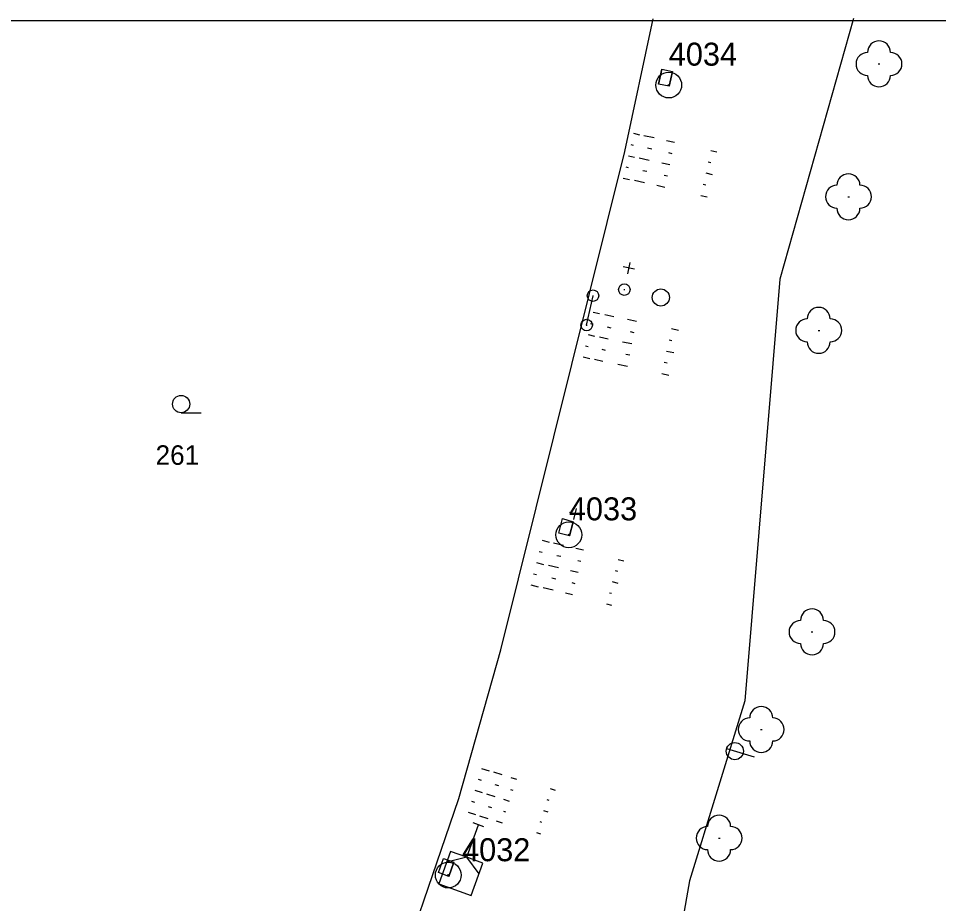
# Model space of a CAD drawing. Extents: x -558358 to -557517, y -1073786 to -1073189.
# Drawn here: x -558098.4 to -558018.3, y -1073267 to -1073189.9 of the extents above; entities that cross this region are included whole.
import ezdxf

# ---------------------------------------------------------------- set-up
doc = ezdxf.new("R2010")
doc.units = 0
for name, color, linetype in [('Body', 7, 'Continuous'), ('bubliny', 7, 'Continuous'), ('Drobná stavba - strom', 7, 'Continuous'), ('Návěst místo trati', 7, 'Continuous'), ('Parcelní čísla', 7, 'Continuous'), ('Přejezd - štěrkové lože', 7, 'Continuous'), ('Sonda - šrafa - vrstevnice', 7, 'Continuous'), ('Svazek obcí údolí Desné', 7, 'Continuous'), ('Vedení nerozlišené', 7, 'Continuous'), ('Vrstva 1', 7, 'Continuous'), ('Vrstva 60', 7, 'Continuous'), ('Značky kultur', 7, 'Continuous')]:
    doc.layers.add(name, color=color, linetype=linetype)

msp = doc.modelspace()

# ---------------------------------------------------------------- linework, layer by layer
at = {"layer": 'Body'}
for p, q in [((-558042.377, -1073194.322), (-558042.666, -1073195.628)), ((-558042.377, -1073194.322), (-558041.446, -1073194.528)), ((-558042.377, -1073194.322), (-558041.446, -1073194.528)), ((-558041.731, -1073195.818), (-558042.666, -1073195.628)), ((-558051.023, -1073233.475), (-558050.106, -1073233.741)), ((-558050.415, -1073234.98), (-558051.35, -1073234.731)), ((-558061.387, -1073263.079), (-558060.495, -1073263.387)), ((-558060.936, -1073264.629), (-558061.833, -1073264.287))]:
    msp.add_line(p, q, dxfattribs=at)
for points in [[(-558042.666, -1073195.628), (-558042.666, -1073195.628), (-558042.377, -1073194.322), (-558042.377, -1073194.322)], [(-558041.446, -1073194.528), (-558041.731, -1073195.818), (-558042.666, -1073195.628)], [(-558041.731, -1073195.818), (-558041.731, -1073195.818), (-558041.446, -1073194.528), (-558041.446, -1073194.528)], [(-558050.106, -1073233.741), (-558050.415, -1073234.98), (-558051.35, -1073234.731), (-558051.023, -1073233.475), (-558050.106, -1073233.741)], [(-558051.35, -1073234.731), (-558051.35, -1073234.731), (-558051.023, -1073233.475), (-558051.023, -1073233.475)], [(-558050.415, -1073234.98), (-558050.415, -1073234.98), (-558050.106, -1073233.741), (-558050.106, -1073233.741)], [(-558060.495, -1073263.387), (-558060.936, -1073264.629), (-558061.833, -1073264.287), (-558061.387, -1073263.079), (-558060.495, -1073263.387)], [(-558061.833, -1073264.287), (-558061.833, -1073264.287), (-558061.387, -1073263.079), (-558061.387, -1073263.079)], [(-558060.936, -1073264.629), (-558060.936, -1073264.629), (-558060.495, -1073263.387), (-558060.495, -1073263.387)]]:
    msp.add_lwpolyline(points, dxfattribs=at)
at = {"layer": 'bubliny'}
for p, q in [((-558048.926, -1073216.62), (-558048.369, -1073214.06)), ((-558048.419, -1073214.06), (-558048.319, -1073214.06)), ((-558048.976, -1073216.62), (-558048.876, -1073216.62))]:
    msp.add_line(p, q, dxfattribs=at)
for centre in [(-558048.369, -1073214.06), (-558048.926, -1073216.62)]:
    msp.add_circle(centre, 0.5, dxfattribs=at)
at = {"layer": 'Drobná stavba - strom'}
for p, q in [((-558023.523, -1073193.881), (-558023.381, -1073193.881)), ((-558026.183, -1073205.447), (-558026.041, -1073205.447)), ((-558028.771, -1073217.083), (-558028.629, -1073217.083)), ((-558029.355, -1073243.343), (-558029.213, -1073243.343)), ((-558033.779, -1073251.838), (-558033.637, -1073251.838)), ((-558037.448, -1073261.298), (-558037.306, -1073261.298))]:
    msp.add_line(p, q, dxfattribs=at)
for centre, start, end in [((-558023.463, -1073192.879), 0, 180), ((-558024.463, -1073193.879), 90, 270), ((-558022.463, -1073193.879), 270, 90), ((-558023.463, -1073194.879), 180, 0), ((-558026.123, -1073204.445), 0, 180), ((-558027.123, -1073205.445), 90, 270), ((-558025.123, -1073205.445), 270, 90), ((-558026.123, -1073206.445), 180, 0), ((-558028.711, -1073216.081), 0, 180), ((-558029.711, -1073217.081), 90, 270), ((-558027.711, -1073217.081), 270, 90), ((-558028.711, -1073218.081), 180, 0), ((-558029.295, -1073242.341), 0, 180), ((-558030.295, -1073243.341), 90, 270), ((-558028.295, -1073243.341), 270, 90), ((-558029.295, -1073244.341), 180, 0), ((-558033.719, -1073250.836), 0, 180), ((-558034.719, -1073251.836), 90, 270), ((-558032.719, -1073251.836), 270, 90), ((-558033.719, -1073252.836), 180, 0), ((-558037.388, -1073260.296), 0, 180), ((-558038.388, -1073261.296), 90, 270), ((-558036.388, -1073261.296), 270, 90), ((-558037.388, -1073262.296), 180, 0)]:
    msp.add_arc(centre, 1, start, end, dxfattribs=at)
at = {"layer": 'Návěst místo trati'}
for p, q in [((-558045.15, -1073211.172), (-558045.36, -1073212.15)), ((-558044.766, -1073211.766), (-558045.744, -1073211.556)), ((-558045.692, -1073213.532), (-558045.592, -1073213.532)), ((-558045.692, -1073213.532), (-558045.592, -1073213.532)), ((-558049.459, -1073233.185), (-558050.429, -1073232.943)), ((-558049.823, -1073232.579), (-558050.065, -1073233.549)), ((-558059.363, -1073262.966), (-558058.344, -1073260.144)), ((-558057.874, -1073260.314), (-558058.814, -1073259.974))]:
    msp.add_line(p, q, dxfattribs=at)
for points in [[(-558059.363, -1073262.966), (-558060.774, -1073262.456), (-558061.794, -1073265.277), (-558058.972, -1073266.297), (-558057.953, -1073263.475), (-558059.363, -1073262.966)], [(-558058.293, -1073264.418), (-558059.363, -1073262.966), (-558061.115, -1073263.398)]]:
    msp.add_lwpolyline(points, dxfattribs=at)
for centre, radius in [((-558045.642, -1073213.532), 0.5), ((-558045.642, -1073213.532), 0.5), ((-558042.463, -1073214.217), 0.75)]:
    msp.add_circle(centre, radius, dxfattribs=at)
at = {"layer": 'Přejezd - štěrkové lože'}
for p, q in [((-558041.26, -1073200.717), (-558041.961, -1073200.566)), ((-558041.471, -1073201.695), (-558041.753, -1073201.634)), ((-558038.115, -1073201.426), (-558037.578, -1073201.545)), ((-558041.682, -1073202.672), (-558042.39, -1073202.519)), ((-558038.333, -1073202.401), (-558038.114, -1073202.45)), ((-558038.55, -1073203.377), (-558037.997, -1073203.501)), ((-558041.893, -1073203.65), (-558042.178, -1073203.588)), ((-558042.104, -1073204.627), (-558042.82, -1073204.473)), ((-558038.768, -1073204.354), (-558038.543, -1073204.404)), ((-558038.986, -1073205.329), (-558038.415, -1073205.457)), ((-558044.575, -1073216.307), (-558045.372, -1073216.145)), ((-558041.54, -1073216.925), (-558040.913, -1073217.06)), ((-558044.774, -1073217.288), (-558045.098, -1073217.221)), ((-558044.974, -1073218.268), (-558045.796, -1073218.1)), ((-558041.751, -1073217.901), (-558041.501, -1073217.955)), ((-558045.174, -1073219.247), (-558045.507, -1073219.179)), ((-558041.962, -1073218.879), (-558041.338, -1073219.014)), ((-558045.374, -1073220.227), (-558046.219, -1073220.055)), ((-558042.172, -1073219.857), (-558041.924, -1073219.91)), ((-558042.383, -1073220.835), (-558041.763, -1073220.968)), ((-558049.189, -1073236.234), (-558049.866, -1073236.064)), ((-558046.192, -1073237.024), (-558045.68, -1073237.155)), ((-558049.432, -1073237.204), (-558049.697, -1073237.137)), ((-558049.676, -1073238.173), (-558050.323, -1073238.011)), ((-558046.439, -1073237.993), (-558046.243, -1073238.044)), ((-558049.92, -1073239.143), (-558050.172, -1073239.08)), ((-558046.687, -1073238.962), (-558046.216, -1073239.082)), ((-558050.164, -1073240.113), (-558050.78, -1073239.959)), ((-558046.934, -1073239.931), (-558046.754, -1073239.977)), ((-558047.182, -1073240.9), (-558046.753, -1073241.01)), ((-558055.003, -1073256.198), (-558055.498, -1073256.033)), ((-558055.319, -1073257.146), (-558055.517, -1073257.08)), ((-558052.087, -1073256.989), (-558051.666, -1073257.123)), ((-558055.634, -1073258.095), (-558056.133, -1073257.929)), ((-558052.39, -1073257.942), (-558052.228, -1073257.994)), ((-558055.95, -1073259.044), (-558056.15, -1073258.977)), ((-558052.693, -1073258.895), (-558052.304, -1073259.019)), ((-558056.265, -1073259.993), (-558056.768, -1073259.825)), ((-558052.996, -1073259.848), (-558052.847, -1073259.896)), ((-558053.299, -1073260.801), (-558052.942, -1073260.915))]:
    msp.add_line(p, q, dxfattribs=at)
at = {"layer": 'Sonda - šrafa - vrstevnice'}
for p, q in [((-558044.85, -1073199.922), (-558044.33, -1073200.04)), ((-558043.041, -1073200.329), (-558043.937, -1073200.133)), ((-558045.07, -1073200.898), (-558044.861, -1073200.945)), ((-558043.255, -1073201.306), (-558043.611, -1073201.228)), ((-558045.29, -1073201.873), (-558044.765, -1073201.992)), ((-558043.469, -1073202.283), (-558044.354, -1073202.089)), ((-558045.511, -1073202.849), (-558045.299, -1073202.897)), ((-558043.683, -1073203.26), (-558044.035, -1073203.183)), ((-558045.731, -1073203.824), (-558045.199, -1073203.944)), ((-558043.897, -1073204.236), (-558044.77, -1073204.045)), ((-558048.357, -1073215.494), (-558047.794, -1073215.62)), ((-558046.562, -1073215.909), (-558047.342, -1073215.719)), ((-558048.576, -1073216.47), (-558048.35, -1073216.521)), ((-558046.8, -1073216.881), (-558047.107, -1073216.806)), ((-558048.794, -1073217.446), (-558048.227, -1073217.573)), ((-558047.037, -1073217.852), (-558047.796, -1073217.667)), ((-558049.012, -1073218.422), (-558048.785, -1073218.473)), ((-558049.231, -1073219.398), (-558048.659, -1073219.525)), ((-558047.274, -1073218.823), (-558047.574, -1073218.75)), ((-558047.511, -1073219.795), (-558048.25, -1073219.615)), ((-558052.807, -1073235.364), (-558052.2, -1073235.52)), ((-558050.945, -1073235.807), (-558051.804, -1073235.613)), ((-558053.055, -1073236.333), (-558052.808, -1073236.397)), ((-558051.166, -1073236.783), (-558051.512, -1073236.704)), ((-558053.302, -1073237.303), (-558052.677, -1073237.463)), ((-558051.387, -1073237.757), (-558052.26, -1073237.559)), ((-558053.55, -1073238.271), (-558053.296, -1073238.336)), ((-558051.608, -1073238.733), (-558051.961, -1073238.653)), ((-558053.798, -1073239.24), (-558053.153, -1073239.405)), ((-558051.829, -1073239.708), (-558052.717, -1073239.507)), ((-558058.083, -1073255.22), (-558057.41, -1073255.425)), ((-558058.373, -1073256.177), (-558058.109, -1073256.258)), ((-558056.282, -1073255.794), (-558057.019, -1073255.561)), ((-558058.664, -1073257.134), (-558058.014, -1073257.332)), ((-558056.584, -1073256.748), (-558056.878, -1073256.655)), ((-558056.885, -1073257.701), (-558057.618, -1073257.469)), ((-558058.954, -1073258.091), (-558058.699, -1073258.168)), ((-558057.187, -1073258.654), (-558057.48, -1073258.561)), ((-558059.245, -1073259.048), (-558058.618, -1073259.238)), ((-558057.489, -1073259.608), (-558058.219, -1073259.377))]:
    msp.add_line(p, q, dxfattribs=at)
at = {"layer": 'Svazek obcí údolí Desné'}
for points in [[(-558082.18, -1073306.93), (-558073.77, -1073292.96), (-558066.53, -1073276.76), (-558060.05, -1073257.85), (-558056.4, -1073244.89), (-558045.6, -1073201.5), (-558043.139, -1073189.962)], [(-558025.68, -1073189.916), (-558032.09, -1073212.63), (-558035.15, -1073249.33), (-558039.97, -1073265.01), (-558041.24, -1073272.26), (-558045.55, -1073290.79), (-558055.77, -1073312.33), (-558066.64, -1073329.29), (-558067.37, -1073328.67), (-558071.91, -1073335.47), (-558071.45, -1073339.78), (-558072.38, -1073341.74), (-558078.52, -1073350.81)]]:
    msp.add_lwpolyline(points, dxfattribs=at)
at = {"layer": 'Vedení nerozlišené'}
msp.add_line((-558036.735, -1073253.503), (-558034.342, -1073254.229), dxfattribs=at)
msp.add_circle((-558036.017, -1073253.721), 0.75, dxfattribs=at)
at = {"layer": 'Vrstva 1'}
msp.add_line((-558357.534, -1073190.088), (-557516.534, -1073190.088), dxfattribs=at)
at = {"layer": 'Vrstva 60'}
for p, q in [((-558041.774, -1073195.717), (-558041.774, -1073195.717)), ((-558041.774, -1073195.717), (-558041.774, -1073195.717)), ((-558050.474, -1073234.883), (-558050.474, -1073234.883)), ((-558050.474, -1073234.883), (-558050.474, -1073234.883)), ((-558060.976, -1073264.511), (-558060.976, -1073264.511)), ((-558060.976, -1073264.511), (-558060.976, -1073264.511))]:
    msp.add_line(p, q, dxfattribs=at)
for centre, radius in [((-558041.774, -1073195.717), 1.125), ((-558041.774, -1073195.717), 0.045), ((-558050.474, -1073234.883), 1.125), ((-558050.474, -1073234.883), 0.045), ((-558060.976, -1073264.511), 1.125), ((-558060.976, -1073264.511), 0.045)]:
    msp.add_circle(centre, radius, dxfattribs=at)
at = {"layer": 'Značky kultur'}
msp.add_line((-558084.243, -1073224.25), (-558082.493, -1073224.25), dxfattribs=at)
msp.add_circle((-558084.243, -1073223.5), 0.75, dxfattribs=at)

# ---------------------------------------------------------------- texts
at = {"layer": 'Parcelní čísla'}
msp.add_text('261', height=1.7, dxfattribs=at).set_placement((-558086.465, -1073228.79))
at = {"layer": 'Vrstva 60'}
for s, p in [('4034', (-558041.774, -1073194.029)), ('4033', (-558050.474, -1073233.624)), ('4032', (-558059.776, -1073263.309))]:
    msp.add_text(s, height=2, dxfattribs=at).set_placement(p)

doc.saveas('drawing.dxf')
